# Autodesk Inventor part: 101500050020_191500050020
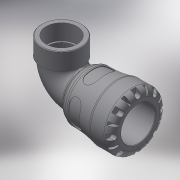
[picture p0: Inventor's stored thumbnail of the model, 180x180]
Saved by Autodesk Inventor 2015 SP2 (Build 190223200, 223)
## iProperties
Created: 2016-12
Part Number: 101500050020_191500050020
Material: Generic
Description: PLASSON 90° ELBOW WITH THREADED FEMALE OFFTAKE 50X2" SERIES 1
Document SubType Name: Modeling
Designer: KIM
Mass: 557.611 g
Surface Area: 990.043 cm^2
Volume: 557.611 cm^3
Density: 1 g/cm^3
Appearance: Default
Author: KIM
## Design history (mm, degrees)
derived "1015.ipt"
feature "Solid1::1015.ipt"
tag "TaggingFeature1"
body "Solid1"
other parameters: "d1" = 33.18, "d3" = 62.5, "d4" = 85, "d8" = 74.8, "d13" = 9, "d14" = 9, "d15" = 0, "d17" = 360 deg, "d19" = 8 deg, "d20" = 1, "d21" = 1, "d22" = 8 deg, "d24" = 0, "d26" = 360 deg, "d33" = 8.5, "d43" = 69.7, "d51" = 0.85, "d54" = 17.5, "d55" = 11, "d57" = 17.64, "d58" = 0, "d74" = 0, "d78" = 79, "d82" = 1, "d115" = 360 deg, "d207" = 90 deg, "d228" = 14.875, "d247" = 1.7, "d248" = 4.74, "d268" = 41.14, "d269" = 4.74, "d270" = 119, "d279" = 75, "d281" = 8.4984, "d294" = 56.656, "d295" = 29, "d296" = 31.9, "d297" = 50.9904, "d299" = 66.28752, "d300" = 50.9904, "d301" = 0, "d302" = 0, "d303" = 1.70624, "d306" = 0, "d307" = 9, "d308" = 8, "d310" = 3, "E_" = 85, "l_" = 79, "A_" = 119, "A_1" = 75, "l_2" = 29, "Rp_" = 56.656, "d9" = 11.25, "d11" = 85, "d12" = 62.5, "d298" = 73.6528
